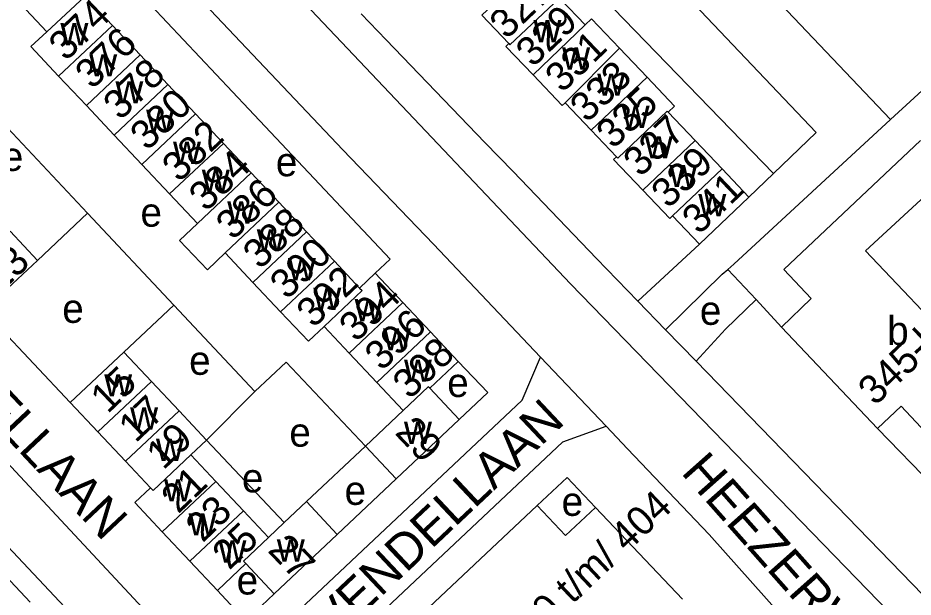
# Model space of a CAD drawing. Extents: x 161258 to 163262, y 380749 to 382054.
# Drawn here: x 162967.6 to 163091.6, y 381299.4 to 381379.6 of the extents above; entities that cross this region are included whole.
import ezdxf

# ---------------------------------------------------------------- set-up
doc = ezdxf.new("R2010")
doc.units = 0
for name, color, linetype in [('BLT_Basislijn', 7, 'Continuous'), ('BLT_Bebouwing', 7, 'Continuous'), ('BLT_Centroide', 7, 'Continuous'), ('BLT_Huisnummer', 7, 'Continuous'), ('BLT_Huisnummer_ tussenligend', 7, 'Continuous'), ('BLT_Huisnummer_reeks', 7, 'Continuous'), ('BLT_Onderverdeling_panden', 7, 'Continuous'), ('BLT_Straatnaam', 7, 'Continuous'), ('BLT_Vlakafsluiter', 7, 'Continuous')]:
    doc.layers.add(name, color=color, linetype=linetype)

msp = doc.modelspace()

# ---------------------------------------------------------------- linework, layer by layer
at = {"layer": 'BLT_Basislijn'}
for p, q in [((163044.15, 381342.79), (162976.64, 381414.05)), ((163046.94, 381409.25), (163088.47, 381365.54)), ((163012.62, 381361.35), (162968.25, 381408.17)), ((163078.15, 381363.74), (163040.52, 381403.36)), ((163032.94, 381398.68), (163072.23, 381358.06)), ((163018.61, 381376.58), (163015.15, 381380.19)), ((163088.47, 381365.54), (163102.96, 381378.91)), ((163032.29, 381362.36), (163018.61, 381376.58)), ((163003.35, 381278.16), (162914.58, 381373.21)), ((162977.25, 381352.55), (162962.08, 381368.7)), ((163072.23, 381358.06), (163078.15, 381363.74)), ((163036.17, 381358.32), (163032.29, 381362.36)), ((163047.74, 381346.28), (163036.17, 381358.32)), ((163068.84, 381354.81), (163072.23, 381358.06)), ((162970.29, 381346.03), (162977.25, 381352.55)), ((162989.2, 381339.82), (162977.25, 381352.55)), ((163053.47, 381340.38), (163061.98, 381348.3)), ((163053.47, 381340.38), (163047.74, 381346.28)), ((163069.86, 381340.64), (163065.91, 381344.78)), ((163073.34, 381336.81), (163069.86, 381340.64)), ((162982.27, 381333.32), (162989.2, 381339.82)), ((162989.2, 381339.82), (163000.42, 381327.87)), ((163057.31, 381336.41), (163053.47, 381340.38)), ((162962.87, 381339.07), (162974.84, 381326.34)), ((163061.54, 381332.06), (163057.31, 381336.41)), ((163037.44, 381326.7), (163039.99, 381332.65)), ((163127.28, 381264.33), (163061.54, 381332.06)), ((163000.42, 381327.87), (162993.73, 381321.14)), ((163043.06, 381320.89), (163049.06, 381323.1)), ((163052.05, 381319.96), (163049.06, 381323.1)), ((163086.67, 381322.74), (163096.16, 381312.93)), ((162993.73, 381321.14), (163004.47, 381309.72)), ((163007.56, 381312.63), (163015.73, 381320.31)), ((163011.83, 381308.1), (163020, 381315.78)), ((162999.15, 381296.16), (162995.23, 381300.33)), ((163003.1, 381299.88), (162999.15, 381296.16))]:
    msp.add_line(p, q, dxfattribs=at)
for points in [[(162979.4, 381384.29), (162981.46, 381386.23), (162999.59, 381366.96), (163019.15, 381346.22), (163017.09, 381344.28)], [(163065.91, 381344.78), (163066.76, 381345.51), (163088.47, 381365.54)], [(163039.99, 381332.65), (163025.18, 381348.26), (163012.62, 381361.35)], [(163057.31, 381336.41), (163065.13, 381344.11), (163065.91, 381344.78)], [(163135.26, 381245.96), (163131.13, 381250.61), (163130.87, 381253.45), (163044.15, 381342.79)], [(163061.54, 381332.06), (163065.6, 381336.51), (163069.86, 381340.64)], [(163000.42, 381327.87), (163004.76, 381331.96), (163015.73, 381320.31)], [(163028.59, 381332.05), (163032.67, 381327.72), (163028.72, 381323.99)], [(162999.15, 381296.16), (163002.56, 381295.52), (163005.84, 381296.97), (163037.44, 381326.7)], [(163043.06, 381320.89), (163011.54, 381291.24), (163009.95, 381288.2), (163010.12, 381284.38)], [(163073.18, 381297.05), (163063.36, 381308.1), (163052.05, 381319.96)], [(163039.53, 381312.08), (163043.68, 381315.98), (163047.58, 381311.83)], [(162984.16, 381287.31), (162963.26, 381309.51)]]:
    msp.add_lwpolyline(points, dxfattribs=at)
at = {"layer": 'BLT_Bebouwing'}
for p, q in [((162968, 381381.49), (162971.58, 381377.68)), ((162977.22, 381382.24), (162980.68, 381378.57)), ((163042.79, 381382.21), (163046.17, 381378.66)), ((162980.68, 381378.57), (162984.53, 381374.49)), ((162971.58, 381377.68), (162969.39, 381375.63)), ((162969.39, 381375.63), (162973.24, 381371.55)), ((163050.91, 381375.42), (163054.73, 381371.4)), ((162984.53, 381374.49), (162988.37, 381370.41)), ((162973.24, 381371.55), (162977.08, 381367.47)), ((162988.37, 381370.41), (162992.21, 381366.33)), ((163047.01, 381364.05), (163043.38, 381367.87)), ((162977.08, 381367.47), (162980.92, 381363.39)), ((162992.21, 381366.33), (162996.06, 381362.24)), ((163057.67, 381366.55), (163061.4, 381362.64)), ((162980.92, 381363.39), (162984.77, 381359.31)), ((163050.51, 381360.37), (163047.01, 381364.05)), ((162996.06, 381362.24), (162999.9, 381358.16)), ((163061.4, 381362.64), (163065.12, 381358.72)), ((162984.77, 381359.31), (162988.61, 381355.23)), ((162999.9, 381358.16), (163003.74, 381354.08)), ((163065.12, 381358.72), (163068.84, 381354.81)), ((162992.45, 381351.15), (162988.61, 381355.23)), ((163068.84, 381354.81), (163061.98, 381348.3)), ((163003.74, 381354.08), (163007.59, 381350)), ((163061.98, 381348.3), (163058.27, 381352.21)), ((162966.5, 381350.06), (162970.29, 381346.03)), ((163007.59, 381350), (163011.43, 381345.92)), ((162970.29, 381346.03), (162962.87, 381339.07)), ((163011.43, 381345.92), (163014.93, 381342.21)), ((163014.93, 381342.21), (163017.09, 381344.28)), ((163017.09, 381344.28), (163020.92, 381340.2)), ((163020.92, 381340.2), (163024.76, 381336.12)), ((163003.98, 381338.91), (163007.83, 381334.83)), ((163007.83, 381334.83), (163010, 381336.88)), ((163010, 381336.88), (163013.48, 381333.2)), ((163028.59, 381332.05), (163024.76, 381336.12)), ((163073.34, 381336.81), (163086.67, 381322.74)), ((162982.27, 381333.32), (162974.84, 381326.34)), ((162986.09, 381329.27), (162982.27, 381333.32)), ((163013.48, 381333.2), (163017.32, 381329.13)), ((163024.64, 381328.33), (163028.59, 381332.05)), ((162986.09, 381329.27), (162989.91, 381325.21)), ((163017.32, 381329.13), (163020.97, 381325.26)), ((163024.64, 381328.33), (163028.72, 381323.99)), ((162974.84, 381326.34), (162978.67, 381322.28)), ((162989.91, 381325.21), (162993.73, 381321.14)), ((163015.73, 381320.31), (163020.97, 381325.26)), ((163028.72, 381323.99), (163020, 381315.78)), ((162993.73, 381321.14), (162991.55, 381319.09)), ((163020, 381315.78), (163015.73, 381320.31)), ((162991.55, 381319.09), (162995, 381315.43)), ((162995, 381315.43), (162998.82, 381311.37)), ((163004.47, 381309.72), (163007.56, 381312.63)), ((163007.56, 381312.63), (163011.83, 381308.1)), ((162998.82, 381311.37), (163002.3, 381307.68)), ((163002.3, 381307.68), (163004.47, 381309.72)), ((162987.59, 381308.44), (162991.41, 381304.39)), ((163011.83, 381308.1), (163003.1, 381299.88)), ((162991.41, 381304.39), (162995.23, 381300.33)), ((162995.23, 381300.33), (162999.18, 381304.05)), ((163003.1, 381299.88), (162999.18, 381304.05))]:
    msp.add_line(p, q, dxfattribs=at)
for points in [[(163042.79, 381382.21), (163043.66, 381383.04), (163039.6, 381387.33), (163031.87, 381379.97), (163035.59, 381376.05)], [(163046.17, 381378.66), (163047.03, 381379.49), (163050.91, 381375.42)], [(163035.59, 381376.05), (163035.19, 381375.67), (163038.94, 381371.73)], [(163043.38, 381367.87), (163042.99, 381367.48), (163038.94, 381371.73)], [(163054.73, 381371.4), (163058.55, 381367.38), (163057.67, 381366.55)], [(163092.63, 381362.65), (163073.69, 381344.79), (163077.49, 381340.76), (163073.34, 381336.81)], [(163054.15, 381355.74), (163050.1, 381359.98), (163050.51, 381360.37)], [(163096.82, 381358.26), (163084.99, 381347.35), (163098.04, 381333.62), (163094.8, 381330.54), (163096.71, 381328.52), (163100.36, 381331.98), (163102.76, 381329.49), (163100.21, 381327.04), (163102.29, 381324.69), (163099.11, 381321.77), (163095.28, 381318.14), (163093.06, 381320.5), (163094.06, 381321.48), (163089.94, 381325.84), (163086.67, 381322.74)], [(163058.27, 381352.21), (163057.87, 381351.83), (163054.15, 381355.74)], [(162992.45, 381351.15), (162989.96, 381348.81), (162993.84, 381344.73), (162996.3, 381347.07)], [(162996.3, 381347.07), (162996.3, 381347.07), (163000.14, 381342.99)], [(163000.14, 381342.99), (163000.14, 381342.99), (163003.98, 381338.91)], [(162978.67, 381322.28), (162978.67, 381322.28), (162982.49, 381318.22)], [(162982.49, 381318.22), (162982.49, 381318.22), (162985.95, 381314.55)], [(162985.95, 381314.55), (162985.95, 381314.55), (162983.77, 381312.49), (162987.59, 381308.44)], [(163039.53, 381312.08), (163014.28, 381288.33)], [(163039.53, 381312.08), (163043.43, 381307.93), (163047.58, 381311.83)], [(163059.66, 381299.11), (163047.58, 381311.83)], [(162965.18, 381303.09), (162969.3, 381298.72)]]:
    msp.add_lwpolyline(points, dxfattribs=at)
at = {"layer": 'BLT_Onderverdeling_panden'}
for p, q in [((162980.68, 381378.57), (162973.24, 381371.55)), ((163046.17, 381378.66), (163038.94, 381371.73)), ((163043.38, 381367.87), (163050.91, 381375.42)), ((162977.08, 381367.47), (162984.53, 381374.49)), ((162988.37, 381370.41), (162980.92, 381363.39)), ((163054.73, 381371.4), (163047.01, 381364.05)), ((162984.77, 381359.31), (162992.21, 381366.33)), ((162996.06, 381362.24), (162988.61, 381355.23)), ((163061.4, 381362.64), (163054.15, 381355.74)), ((162999.9, 381358.16), (162992.45, 381351.15)), ((163058.27, 381352.21), (163065.12, 381358.72)), ((162996.3, 381347.07), (163003.74, 381354.08)), ((163007.59, 381350), (163000.14, 381342.99)), ((163003.98, 381338.91), (163011.43, 381345.92)), ((163013.48, 381333.2), (163020.92, 381340.2)), ((163017.32, 381329.13), (163024.76, 381336.12)), ((162978.67, 381322.28), (162986.09, 381329.27)), ((162989.91, 381325.21), (162982.49, 381318.22)), ((162987.59, 381308.44), (162995, 381315.43)), ((162991.41, 381304.39), (162998.82, 381311.37))]:
    msp.add_line(p, q, dxfattribs=at)
for points in [[(162971.58, 381377.68), (162976.85, 381382.64), (162977.22, 381382.24)], [(163035.59, 381376.05), (163035.75, 381375.87), (163042.61, 381382.4), (163042.79, 381382.21)], [(163050.51, 381360.37), (163050.67, 381360.2), (163057.52, 381366.71), (163057.67, 381366.55)], [(163014.93, 381342.21), (163015.27, 381341.85), (163010, 381336.88)], [(163024.64, 381328.33), (163024.44, 381328.53), (163020.97, 381325.26)], [(162985.95, 381314.55), (162986.32, 381314.16), (162991.55, 381319.09), (162991.55, 381319.09)], [(162999.18, 381304.05), (162998.84, 381304.41), (163002.3, 381307.68)]]:
    msp.add_lwpolyline(points, dxfattribs=at)
at = {"layer": 'BLT_Vlakafsluiter'}
msp.add_line((163049.06, 381323.1), (163039.99, 381332.65), dxfattribs=at)

# ---------------------------------------------------------------- texts
at = {"layer": 'BLT_Centroide'}
for s, p in [('w', (163039, 381376.24)), ('w', (162973.48, 381375.81)), ('w', (163042.98, 381372.44)), ('w', (162977.48, 381371.5)), ('w', (163047.83, 381368.82)), ('w', (162981.1, 381367.77)), ('w', (162985.36, 381363.82)), ('w', (163051.22, 381364.38)), ('w', (163054.43, 381360.16)), ('w', (162989.08, 381359.4)), ('e', (162965.37, 381358.42)), ('e', (163003.32, 381357.68)), ('w', (163057.81, 381356.18)), ('w', (162993.07, 381355.51)), ('w', (162996.59, 381351.14)), ('w', (163061.84, 381352.15)), ('e', (162984.57, 381350.7)), ('w', (163000.68, 381347.28)), ('w', (163004.99, 381343.28)), ('w', (163008.51, 381339.17)), ('w', (163014.24, 381337.6)), ('e', (162973.74, 381337.38)), ('e', (163062.05, 381337.11)), ('b', (163088, 381334.3)), ('w', (163018.17, 381333.56)), ('e', (162991.31, 381330.19)), ('w', (163021.07, 381329.23)), ('w', (162979.55, 381327.2)), ('e', (163027.06, 381327.12)), ('w', (162983.14, 381322.6)), ('e', (163005.19, 381320.24)), ('w', (163021.07, 381320.62)), ('w', (162986.72, 381318.27)), ('e', (162998.62, 381313.92)), ('w', (162987.83, 381312.66)), ('e', (163012.84, 381312.18)), ('e', (163042.9, 381310.66)), ('w', (162991.23, 381307.96)), ('w', (162995.37, 381304.19)), ('w', (163003.46, 381304.33)), ('e', (162997.89, 381299.77))]:
    msp.add_text(s, height=4, dxfattribs=at).set_placement(p)
at = {"layer": 'BLT_Huisnummer'}
for s, rotation, p in [('327', 43.5965, (163035.28, 381376.52)), ('376', 43.6052, (162977.88, 381369.6)), ('331', 43.5965, (163042.98, 381369.12)), ('380', 43.6052, (162985.5, 381361.09)), ('335', 43.5965, (163050.06, 381361.34)), ('384', 43.6052, (162993.64, 381352.65)), ('339', 43.5965, (163057.68, 381353.09)), ('341', 43.5965, (163061.94, 381349.48)), ('388', 43.6052, (163001.12, 381344.66)), ('13', 43.6052, (162965.16, 381341.45)), ('392', 43.6052, (163008.54, 381336.56)), ('396', 43.6052, (163017.99, 381330.6)), ('398', 43.6052, (163021.86, 381326.67)), ('15', 43.6052, (162980.02, 381324.7)), ('19', 43.6052, (162987.74, 381316.91)), ('29', 313.6052, (163019.68, 381322.08)), ('23', 43.6052, (162993.18, 381306.85)), ('25', 43.6052, (162996.87, 381303.06)), ('27', 313.6052, (163002.07, 381305.79))]:
    msp.add_text(s, height=4, rotation=rotation, dxfattribs=at).set_placement(p)
at = {"layer": 'BLT_Huisnummer_ tussenligend'}
for s, rotation, p in [('374', 43.6052, (162974.23, 381373.5)), ('329', 43.5965, (163038.92, 381372.64)), ('378', 43.6052, (162981.77, 381365.3)), ('333', 43.5965, (163046.42, 381364.98)), ('337', 43.5965, (163053.8, 381357.44)), ('382', 43.6052, (162989.92, 381356.72)), ('386', 43.6052, (162997.38, 381348.71)), ('390', 43.6052, (163004.86, 381340.48)), ('394', 43.6052, (163014.44, 381334.59)), ('17', 43.6052, (162983.9, 381320.67)), ('21', 43.6052, (162989.8, 381310.85))]:
    msp.add_text(s, height=4, rotation=rotation, dxfattribs=at).set_placement(p)
at = {"layer": 'BLT_Huisnummer_reeks'}
for s, rotation, p in [('345-b t/m p', 43.6425, (163086.33, 381325.79)), ('400 t/m/ 404', 43.2724, (163036.8, 381291.23))]:
    msp.add_text(s, height=4, rotation=rotation, dxfattribs=at).set_placement(p)
at = {"layer": 'BLT_Straatnaam'}
for s, rotation, p in [('LAVENDELLAAN', 313.275, (162943.58, 381345.16)), ('LAVENDELLAAN', 43.2766, (163005.39, 381287.64)), ('HEEZERWEG', 311.591, (163059.33, 381316.61))]:
    msp.add_text(s, height=5, rotation=rotation, dxfattribs=at).set_placement(p)

doc.saveas('drawing.dxf')
